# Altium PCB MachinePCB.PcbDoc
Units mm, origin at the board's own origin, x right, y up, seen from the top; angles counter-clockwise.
Board outline 152.4 x 101.6 mm, 2 copper layers (Top Layer, Bottom Layer); 66 components, 31 nets, 228 pads, 37 vias.
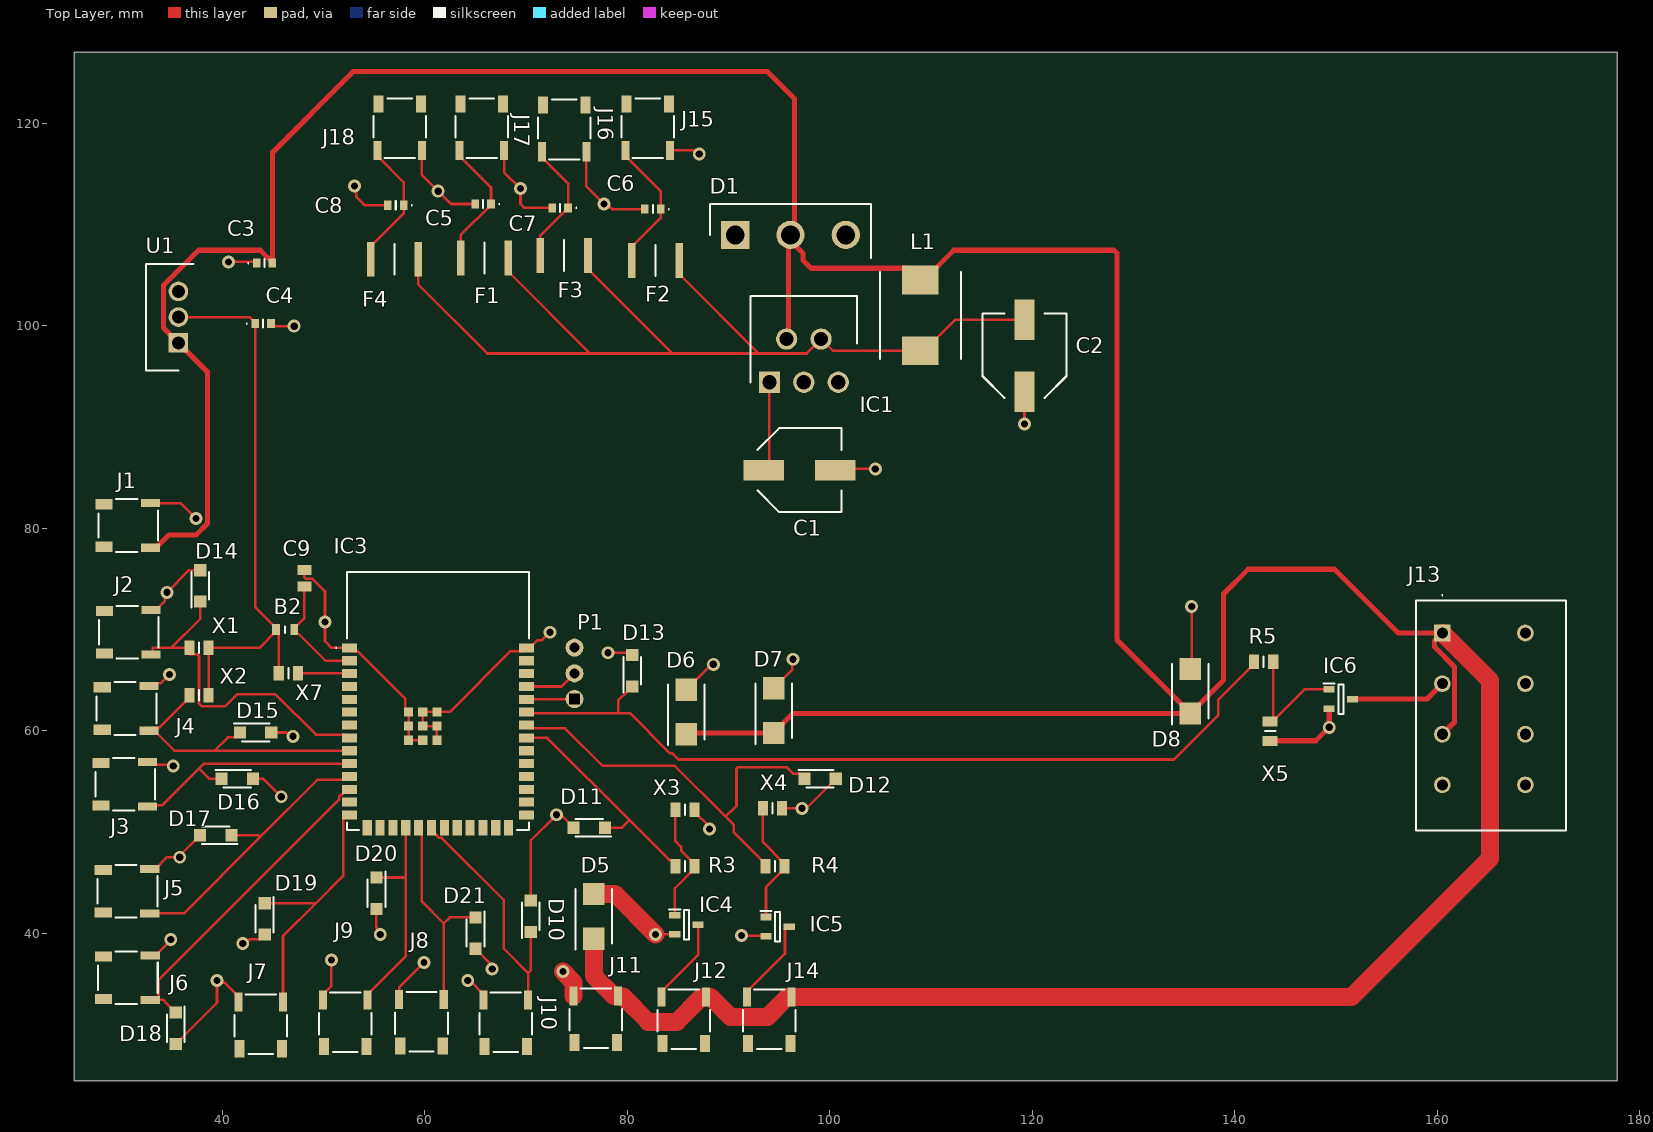
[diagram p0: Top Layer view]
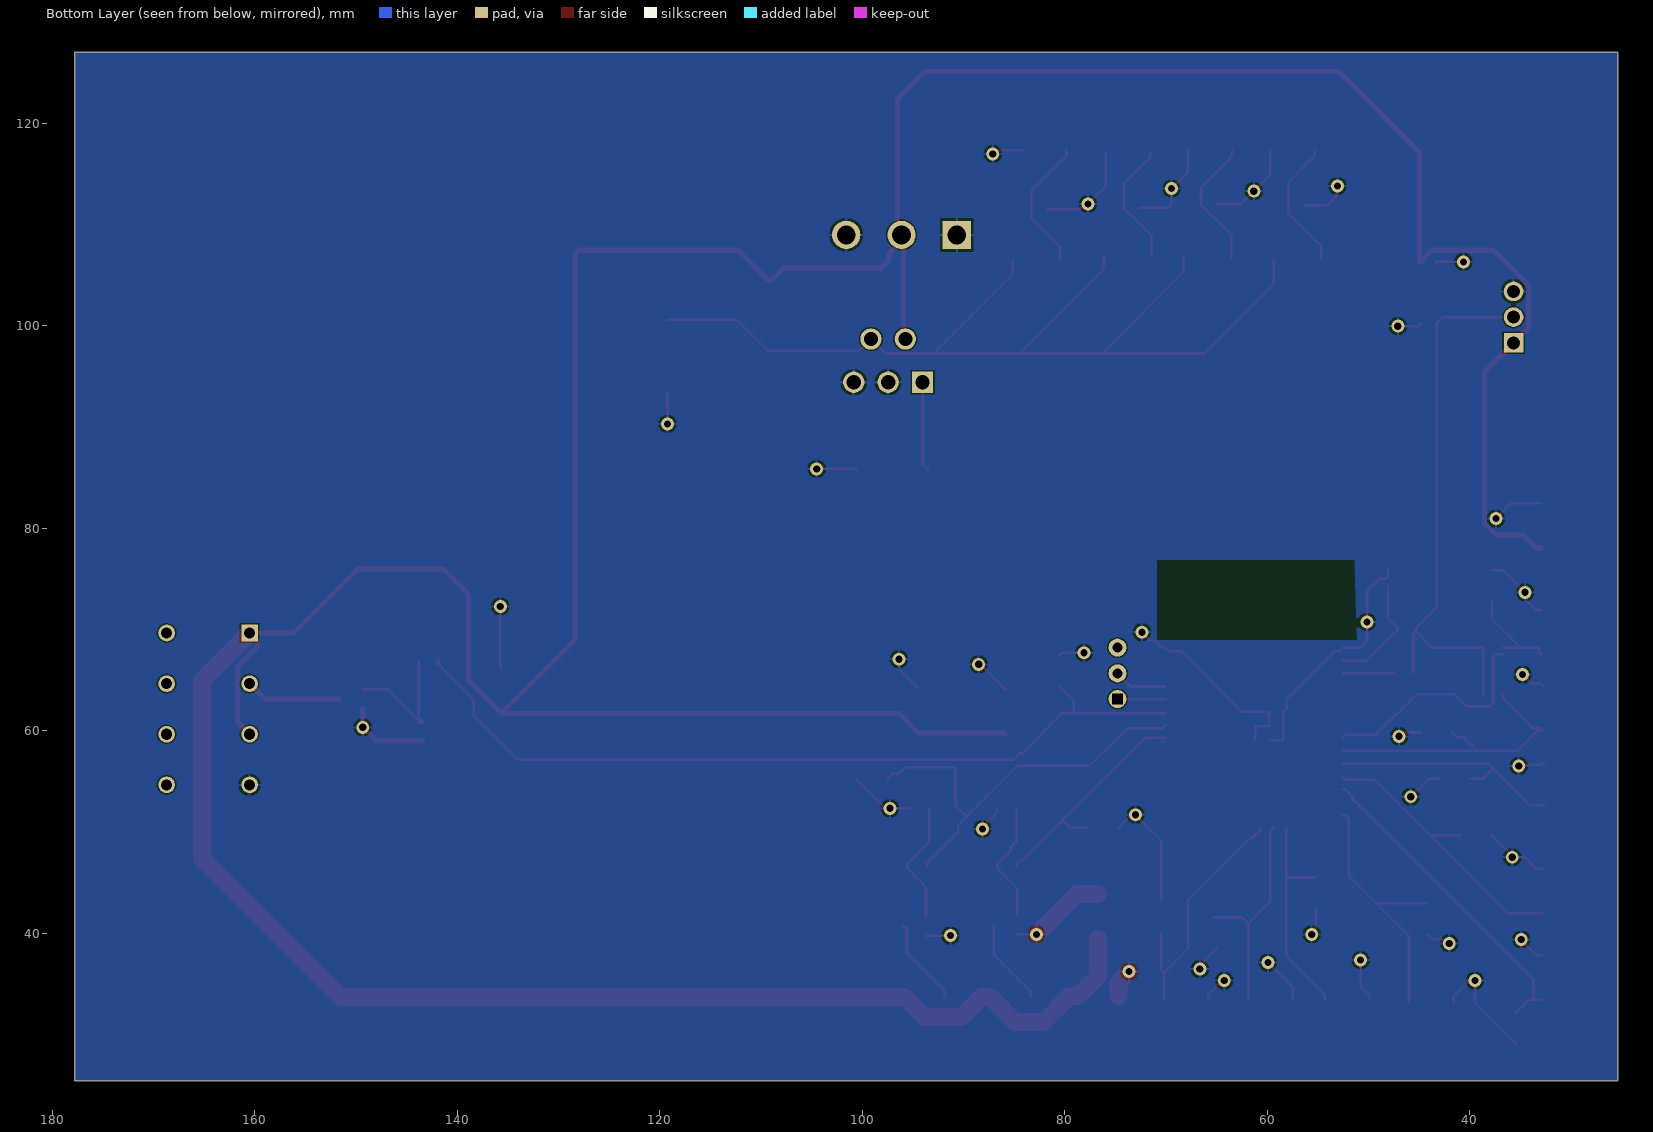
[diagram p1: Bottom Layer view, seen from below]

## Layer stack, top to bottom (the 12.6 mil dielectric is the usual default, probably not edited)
Top Solder: solder mask 0.0102, Solder Resist, Dk 3.5
Top Layer: signal copper 0.0356
Dielectric 1: dielectric 0.32, FR-4, Dk 4.8
Bottom Layer: signal copper 0.0356
Bottom Solder: solder mask 0.0102, Solder Resist, Dk 3.5

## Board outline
25.4,25.4 177.8,25.4 177.8,127 25.4,127

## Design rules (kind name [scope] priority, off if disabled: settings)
Clearance [All] p1: gap=0.127 ignorepadtopadclearanceinfootprint=FALSE
PolygonConnect [All] p1: connectstyle=Relief reliefconductorwidth=0.254 reliefentries=4 polygonreliefangle="90 Angle" airgapwidth=0.254
RoutingVias [All] p1: holewidth=0.711 width=1.27 viastyle="Through Hole" minholewidth=0.711 minwidth=1.27 maxholewidth=0.711 maxwidth=1.27
SilkToSolderMaskClearance [IsPad] p1: minsilkscreentomaskgap=0.051 clearancetoexposedcopper=TRUE
SolderMaskExpansion [All] p1: expansion=0.05 istentingtop=FALSE
SupplyNets "Schematic Supply Nets" [InNet('GND')] p1: voltage=0.000
Width [All] p1: maxlimit=2.54 minlimit=0.254 preferedwidth=0.254 bottomlayer_maxwidth=0.254 minimp=50.000000 maximp=50.000000 favimp=50.000000
29 further rules are at their usual default settings.

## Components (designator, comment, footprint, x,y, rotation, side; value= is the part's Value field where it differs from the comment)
B2 "MF-FSML100_8-2" FUSC1608X70N 46.228,69.977 r0 top
C1 "220 uF" EEHZT1E331UP 97.028,85.725 r0 top
C2 "220 uF" EEHZT1E331UP 119.253,97.028 r90 top
C3 "10 uF" ZRB18x 44.196,106.172 r0 top
C4 "10 uF" ZRB18x 44.056,100.203 r0 top
C5 "ZRB18AR61E106KE01L" ZRB18x 65.786,112.014 r180 top
C6 "ZRB18AR61E106KE01L" ZRB18x 82.537,111.506 r180 top
C7 "ZRB18AR61E106KE01L" ZRB18x 73.393,111.633 r180 top
C8 "ZRB18AR61E106KE01L" ZRB18x 57.15,111.887 r180 top
C9 "0.1 uF" CAPC2012X125N 48.133,75.057 r270 top
D1 "VS-40CPQ045-N3" TO546P531X1558X2499-3P 90.679,108.966 r0 top
D5 "TPSMB12A-VR" DIOM5436X244N 76.708,41.656 r90 top
D6 "TPSMB12A-VR" DIOM5436X244N 85.852,61.849 r90 top
D7 "TPSMB12A-VR" DIOM5436X244N 94.488,61.976 r90 top
D8 "TPSMB12A-VR" DIOM5436X244N 135.636,63.881 r90 top
D10 "SMF5.0A" SODFL3618X110N 70.485,41.656 r90 top
D11 "SMF5.0A" SODFL3618X110N 76.271,50.412 r180 top
D12 "SMF5.0A" SODFL3618X110N 99.06,55.245 r0 top
D13 "SMF5.0A" SODFL3618X110N 80.518,65.913 r90 top
D14 "SMF5.0A" SODFL3618X110N 37.846,74.295 r90 top
D15 "SMF5.0A" SODFL3618X110N 43.307,59.817 r0 top
D16 "SMF5.0A" SODFL3618X110N 41.503,55.245 r0 top
D17 "SMF5.0A" SODFL3618X110N 39.37,49.657 r180 top
D18 "SMF5.0A" SODFL3618X110N 35.433,30.607 r270 top
D19 "SMF5.0A" SODFL3618X110N 44.196,41.402 r270 top
D20 "SMF5.0A" SODFL3618X110N 55.245,43.942 r270 top
D21 "SMF5.0A" SODFL3618X110N 65.024,40.005 r270 top
F1 "PTS18126V300" FUSC4632X120N#1 65.913,106.68 r180 top
F2 "PTS18126V300" FUSC4632X120N#1 82.804,106.426 r180 top
F3 "PTS18126V300" FUSC4632X120N#2 73.787,106.934 r180 top
F4 "PTS18126V300" FUSC4632X120N#1 57.023,106.553 r180 top
IC1 "LM2596T-5.0_LF03" TO170P470X1028X2142-5P 94.058,94.409 r0 top
IC3 "ESP32-S3-WROOM-1-N4" ESP32S3WROOM1N4 61.317,62.662 r0 top
IC4 "NDS355AN" SOT95P251X112-3N 85.859,40.828 r0 top
IC5 "NDS355AN" SOT95P251X112-3N 94.869,40.64 r0 top
IC6 "NDS355AN" SOT95P251X112-3N 150.495,63.119 r0 top
J1 "SM02B-SFHLS-TF_LF__SN_" SM02BSFHLSTFLFSN 30.734,80.264 r180 top
J2 "SM02B-SFHLS-TF_LF__SN_" SM02BSFHLSTFLFSN 30.779,69.723 r180 top
J3 "SM02B-SFHLS-TF_LF__SN_" SM02BSFHLSTFLFSN 30.439,54.696 r180 top
J4 "SM02B-SFHLS-TF_LF__SN_" SM02BSFHLSTFLFSN 30.566,62.189 r180 top
J5 "SM02B-SFHLS-TF_LF__SN_" SM02BSFHLSTFLFSN 30.661,44.148 r180 top
J6 "SM02B-SFHLS-TF_LF__SN_" SM02BSFHLSTFLFSN 30.693,35.601 r180 top
J7 "SM02B-SFHLS-TF_LF__SN_" SM02BSFHLSTFLFSN 43.815,30.988 r270 top
J8 "SM02B-SFHLS-TF_LF__SN_" SM02BSFHLSTFLFSN 59.69,31.242 r270 top
J9 "SM02B-SFHLS-TF_LF__SN_" SM02BSFHLSTFLFSN 52.156,31.201 r270 top
J10 "SM02B-SFHLS-TF_LF__SN_" SM02BSFHLSTFLFSN 68.031,31.201 r270 top
J11 "SM02B-SFHLS-TF_LF__SN_" SM02BSFHLSTFLFSN 76.921,31.582 r270 top
J12 "SM02B-SFHLS-TF_LF__SN_" SM02BSFHLSTFLFSN 85.598,31.496 r270 top
J13 "1330200000" 1330200000 160.528,69.643 r270 top
J14 "SM02B-SFHLS-TF_LF__SN_" SM02BSFHLSTFLFSN 94.048,31.483 r270 top
J15 "SM02B-SFHLS-TF_LF__SN_" SM02BSFHLSTFLFSN 82.042,119.507 r90 top
J16 "SM02B-SFHLS-TF_LF__SN_" SM02BSFHLSTFLFSN 73.787,119.38 r90 top
J17 "SM02B-SFHLS-TF_LF__SN_" SM02BSFHLSTFLFSN 65.659,119.507 r90 top
J18 "SM02B-SFHLS-TF_LF__SN_" SM02BSFHLSTFLFSN 57.531,119.507 r90 top
L1 "33 uH" INDPM8680X400N 108.966,101.021 r270 top
P1 "PREC003SAAN-RC" PCBComponent_1 74.803,65.659 r90 top
R3 "100" RESC2012X55N 85.725,46.609 r0 top
R4 "100" RESC2012X55N 94.615,46.609 r0 top
R5 "100" RESC2012X55N 142.875,66.802 r0 top
U1 "LMS1585ACT-3.3_NOPB" TO254P470X1028X1955-3P 35.687,98.298 r90 top
X1 "4.7k" RESC2012X65N 37.719,68.172 r0 top
X2 "4.7k" RESC2012X65N 37.719,63.5 r0 top
X3 "4.7k" RESC2012X65N 85.725,52.197 r0 top
X4 "4.7k" RESC2012X65N 94.361,52.324 r0 top
X5 "4.7k" RESC2012X65N 143.51,59.944 r270 top
X7 "4.7k" RESC2012X65N 46.543,65.659 r180 top

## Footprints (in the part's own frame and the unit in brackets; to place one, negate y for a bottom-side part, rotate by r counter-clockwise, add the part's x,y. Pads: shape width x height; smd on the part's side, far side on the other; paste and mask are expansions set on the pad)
1330200000 [mm]
  rect 1.65x1.65 hole 1.1: A1(0,0)
  round 1.65 hole 1.1: A2(5,0) A3(10,0) A4(15,0) B1(0,8.2) B2(5,8.2) B3(10,8.2) B4(15,8.2)
  silkscreen extent -3.8,-2.6 19.5,12.2
CAPC2012X125N [mm]
  rect 0.99x1.39 smd: 1(-0.82,0) 2(0.82,0)
DIOM5436X244N [mm]
  rect 2.2x2.15 smd: 1(-2.2,0) 2(2.2,0)
  silkscreen extent -3.27,-1.81 2.7,1.81, body extent -2.7,-1.81 2.7,1.81, height 2.44
EEHZT1E331UP [mm]
  rect 4x2 smd: 1(-3.55,0) 2(3.55,0)
  silkscreen extent -4.15,-4.15 4.15,4.15, body extent -4.79,-4.15 4.91,4.15, height 10.2
ESP32S3WROOM1N4 [mm]
  rect 1.5x0.9 smd: 1(-8.75,5.51) 2(-8.75,4.24) 3(-8.75,2.97) 4(-8.75,1.7) 5(-8.75,0.43) 6(-8.75,-0.84) 7(-8.75,-2.11) 8(-8.75,-3.38) 9(-8.75,-4.65) 10(-8.75,-5.92) 11(-8.75,-7.19) 12(-8.75,-8.46) 13(-8.75,-9.73) 14(-8.75,-11) 27(8.75,-11) 28(8.75,-9.73) 29(8.75,-8.46) 30(8.75,-7.19) 31(8.75,-5.92) 32(8.75,-4.65) 33(8.75,-3.38) 34(8.75,-2.11) 35(8.75,-0.84) 36(8.75,0.43) 37(8.75,1.7) 38(8.75,2.97) 39(8.75,4.24) 40(8.75,5.51)
  rect 0.9x1.5 smd: 15(-6.985,-12.25) 16(-5.715,-12.25) 17(-4.445,-12.25) 18(-3.175,-12.25) 19(-1.905,-12.25) 20(-0.635,-12.25) 21(0.635,-12.25) 22(1.905,-12.25) 23(3.175,-12.25) 24(4.445,-12.25) 25(5.715,-12.25) 26(6.985,-12.25)
  rect 0.9x0.9 smd: 41(-1.5,-2.21) 42(-0.1,-2.21) 43(-0.1,-0.81) 44(-1.5,-0.81) 45(-2.9,-0.81) 46(-2.9,-2.21) 47(-2.9,-3.61) 48(-1.5,-3.61) 49(-0.1,-3.61)
  silkscreen extent -10.1,-12.5 9,13
FUSC1608X70N [mm]
  rect 0.77x1.07 smd: 1(-0.9,0) 2(0.9,0)
  silkscreen extent 0,-0.33 0,0.33
FUSC4632X120N#1 [mm]
  rect 0.75x3.43 smd: 1(-2.35,0) 2(2.35,0)
  silkscreen extent 0,-1.52 0,1.52
FUSC4632X120N#2 [mm]
  rect 0.75x3.43 smd: 1(-2.35,0) " "(2.35,0)
  silkscreen extent 0,-1.52 0,1.52
INDPM8680X400N [mm]
  rect 2.85x3.6 smd: 1(-3.5,0) 2(3.5,0)
  silkscreen extent -4.3,-4 4.3,4
PCBComponent_1 [mm]
  round 1.78 hole 1 square: 1(-2.54,0)
  round 1.78 hole 1: 2(0,0) 3(2.54,0)
RESC2012X55N [mm]
  rect 1x1.45 smd: 1(-0.95,0) 2(0.95,0)
  silkscreen extent 0,-0.53 0,0.53
RESC2012X65N [mm]
  rect 1x1.45 smd: 1(-0.95,0) 2(0.95,0)
  silkscreen extent 0,-0.53 0,0.53
SM02BSFHLSTFLFSN [mm]
  rect 1.7x1 smd: 1(2.4,2.1) 2(2.4,-2.1)
  rect 1.9x0.8 smd: MP1(-2.2,2.2) MP2(-2.2,-2.2)
  silkscreen extent -2.95,-2.6 2.95,2.6
SODFL3618X110N [mm]
  rect 1.2x1.22 smd: 1(-1.55,0) 2(1.55,0)
  silkscreen extent -2.15,-0.87 1.35,0.87
SOT95P251X112-3N [mm]
  rect 1.1x0.65 smd: 1(-1.15,0.95) 2(-1.15,-0.95) 3(1.15,0)
  silkscreen extent -1.7,-1.46 0.25,1.53
TO170P470X1028X2142-5P [mm]
  rect 2.1x2.1 / inner round 2.1 / far side rect 2.1x2.1 hole 1.4: 1(0,0)
  round 2.1 hole 1.4: 2(1.7,4.27) 3(3.4,0) 4(5.1,4.27) 5(6.8,0)
  silkscreen extent -1.87,0 8.67,8.53
TO254P470X1028X1955-3P [mm]
  rect 1.935x1.935 / inner round 1.935 / far side rect 1.935x1.935 hole 1.29: 1(0,0)
  round 1.935 hole 1.29: 2(2.54,0) 3(5.08,0)
  silkscreen extent -2.73,-1.5 7.81,3.2
TO546P531X1558X2499-3P [mm]
  rect 2.79x2.79 / inner round 2.79 / far side rect 2.79x2.79 hole 1.86: 1(0,0)
  round 2.79 hole 1.86: 2(5.46,0) 3(10.92,0)
  silkscreen extent -2.47,-2.27 13.39,3.04
ZRB18x [mm]
  rect 0.75x0.9 smd: 1(-0.775,0) 2(0.775,0)
  silkscreen extent -1.65,-0.4 0,0.4

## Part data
B2: "Resettable Fuses - PPTC 8V     1A", Manufacturer_Name=Bourns, Manufacturer_Part_Number=MF-FSML100/8-2, Mouser Part Number=652-MF-FSML100/8-2
C1 C2: library part EEE-TP1C221AP, "Capacitor Polarised", Manufacturer_Name=Panasonic, Mouser Part Number=667-EEE-TP1C221AP
C3 C4: library part ZRB18AR61E106KE01L, Manufacturer_Name="Murata Electronics"
C5 C6 C7 C8: "Capacitor", Manufacturer_Name="Murata Electronics"
C9: library part 885382207007, "WCAP-CSST Soft Termination MLCC X7R0805104K050DFCT1S000; SMT Chip; 100 nF +/- 10%; 50 V(DC); -55C / +125C; size 0805; LxWxH 2.0 x 1.25 x 1.25; Term. Ag-Polymer/Ni/Sn", Manufacturer_Name="Wurth Elektronik", Mouser Part Number=710-885382207007
D1: "Diode", Manufacturer_Name=Vishay, Mouser Part Number=78-VS-40CPQ045-N3
D5 D6 D7 D8: "TVS Diode (Uni-directional)", Manufacturer_Name=LITTELFUSE, Mouser Part Number=576-TPSMB12A-VR
D10 D11 D12 D13 D14 D15 D16 D17 D18 D19 D20 D21: "LITTELFUSE - SMF5.0A - TVS DIODE, 200W, 5V, UNIDIR, SOD-123FL", Manufacturer_Name=LITTELFUSE, Mouser Part Number=576-SMF5.0A
F1 F2 F3 F4: "PPTC SMD 1812 6V 3.0A", Manufacturer_Name=Eaton, Mouser Part Number=504-PTS18126V300
IC1: "Integrated Circuit", Arrow Part Number=LM2596T-5.0/LF03, Manufacturer_Name="Texas Instruments", Mouser Part Number=926-LM2596T-50/LF03
IC3: "Integrated Circuit", Manufacturer_Name="Espressif Systems", Mouser Part Number=356-ESP32-S3WROOM1N4
IC4 IC5 IC6: "Integrated Circuit", Manufacturer_Name=onsemi, Mouser Part Number=512-NDS355AN
J1 J2 J3 J4 J5 J6 J7 J8 J9 J10 J11 J12 J14 J15 J16 J17 J18: "CONN HEADER SMD R/A 2POS 1.8MM", Manufacturer_Name="JST (JAPAN SOLDERLESS TERMINALS)", Manufacturer_Part_Number=SM02B-SFHLS-TF(LF)(SN), Mouser Part Number=306-SM02BSFHLSTFLFSN
J13: "Connector", Manufacturer_Name=Weidmuller, Mouser Part Number=470-1330200000
L1: library part F1F2-0804-330M, "Inductor", Manufacturer_Name=Bel
P1: "ESP32 USB Connector"
R3 R4 R5: library part TNPW0805100RBEEA, "Resistor", Manufacturer_Name=Vishay, Mouser Part Number=71-TNPW0805100RBEEA
U1: "Undefined or Miscellaneous", Arrow Part Number=LMS1585ACT-3.3/NOPB, Manufacturer_Name="Texas Instruments", Mouser Part Number=926-LMS1585ACT33NOPB
X1 X2 X3 X4 X5 X7: library part CPF0805B4K7E1, Manufacturer_Name="TE Connectivity", Mouser Part Number=279-CPF0805B4K7E1

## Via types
v1: diameter 1.27, hole 0.711, Top Layer to Bottom Layer, 37 vias

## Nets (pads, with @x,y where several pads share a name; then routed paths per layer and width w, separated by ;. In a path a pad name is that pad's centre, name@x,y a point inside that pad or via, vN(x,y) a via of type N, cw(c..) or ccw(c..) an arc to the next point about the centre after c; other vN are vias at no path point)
12_IN: C3.2 D1.2 D5.1 D6.1 D7.1 D8.1 IC1.2 J1.MP1 J11.MP1 J12.MP1 J13.A1 J13.A3 J14.MP1 L1.1 U1.1 | length 445.3
  Top Layer w0.508: J1.MP1 33.484,78.064 34.758,79.338 37.441,79.338 38.568,80.465 38.568,95.417 U1.1 34.211,99.774 34.211,103.989 37.664,107.442 43.776,107.442 44.971,106.247 C3.2 44.971,117.107 52.959,125.095 93.853,125.095 96.52,122.428 96.52,109.347 D1.2 ; D6.1 85.979,59.776 D7.1 ; D7.1@94.488,59.801 96.368,61.681 D8.1 D8.1@135.636,61.706 ; IC1.2 95.948,98.87 D1.2@95.948,108.384 ; D1.2@96.139,108.384 97.373,107.15 97.373,106.462 98.171,105.664 107.823,105.664 L1.1 109.341,104.521 112.262,107.442 128.099,107.442 128.397,107.144 128.397,68.945 D8.1@135.636,61.706 ; J13.A3 161.734,60.849 161.734,66.29 159.766,68.258 159.766,68.881 J13.A1 156.163,69.643 149.86,75.946 141.351,75.946 138.904,73.499 138.904,64.974 D8.1@135.636,61.706
  Top Layer w1.778: D5.1@76.708,39.431 76.708,35.767 78.693,33.782 J11.MP1 ; 79.61,33.721 82.089,31.242 84.916,31.242 87.309,33.635 ; J12.MP1 88.226,33.696 90.205,31.717 93.854,31.717 95.82,33.683 J14.MP1 151.539,33.683 165.227,47.371 165.227,64.944 J13.A1
+3.3V: B2.1 C4.1 U1.2 X1.2 X2.2 X7.2 | length 55.3
  Top Layer w0.254: U1.2 42.721,100.838 43.281,100.278 C4.1 43.281,72.174 45.328,70.127 B2.1 ; X2.2 X1.2 43.673,68.172 45.328,69.827 45.593,69.562 X7.2
+5V: C2.2 F1.1 F2.1 F3.1 F4.1 IC1.4 L1.2 | length 105.9
  Top Layer w0.254: F4.1 59.373,104.076 66.201,97.248 76.355,97.248 ; F1.1 68.263,105.34 76.355,97.248 ; F3.1 76.137,105.594 84.483,97.248 ; F2.1 85.154,105.086 92.992,97.248 ; C2.2 112.398,100.578 109.341,97.521 L1.2 100.316,97.521 IC1.4 97.727,97.248 92.992,97.248 ; 76.355,97.248 84.483,97.248 ; 84.483,97.248 92.992,97.248
FLOW: D15.1 IC3.9 J4.MP1 X2.1 | length 29.1
  Top Layer w0.254: J4.MP1 33.316,59.989 35.293,58.012 39.243,58.012 ; J4.MP1@33.039,60.262 33.756,60.262 36.769,63.275 X2.1 ; D15.1 41.757,59.807 41.284,59.334 40.565,59.334 39.243,58.012 ; IC3.9 39.243,58.012
GND: C1.2 C2.1 C3.1 C4.2 C5.2 C6.2 C7.2 C8.2 C9.1 D1.1 D1.3 D5.2 D6.2 D7.2 D8.2 D10.2 D11.2 D12.2 D13.2 D14.2 D15.2 D16.2 D17.2 D18.2 D19.2 D20.2 D21.2 IC1.3 IC1.5 IC3.1 IC3.40 IC3.41 IC3.42 IC3.43 IC3.44 IC3.45 IC3.46 IC3.47 IC3.48 IC3.49 IC4.2 IC5.2 IC6.2 J1.MP2 J2.MP2 J3.MP2 J4.MP2 J5.MP2 J6.MP2 J7.MP2 J8.MP2 J9.MP2 J10.MP2 J11.MP2 J13.A4 J15.MP2 J16.MP2 J17.MP2 J18.MP2 U1.3 X3.2 X4.2 X5.2 | length 215.6
  Top Layer w0.254: J3.MP2 32.912,56.623 35.071,56.623 v1(35.179,56.515) ; J4.MP2 33.039,64.662 33.928,64.662 v1(34.798,65.532) ; J5.MP2 33.411,46.348 34.561,47.498 v1(35.814,47.498) 35.814,47.641 37.82,49.647 D17.2 ; J6.MP2 33.443,37.801 34.925,39.283 v1(34.925,39.37) ; J2.MP2@32.934,71.923 33.484,71.923 34.35,72.789 34.35,73.466 v1(34.544,73.66) 36.729,75.845 D14.2 ; J1.MP2 35.9,82.464 v1(37.425,80.939) ; D18.2 35.443,29.057 35.916,29.53 35.916,29.54 39.497,33.121 v1(39.497,35.306) 39.691,35.112 40.241,35.112 41.615,33.738 J7.MP2 ; v1(40.64,106.299) 43.294,106.299 C3.1 ; v1(42.037,38.989) 42.312,38.989 42.702,39.379 43.723,39.379 D19.2 ; D16.2 44.069,55.245 v1(45.847,53.467) ; C4.2 44.831,100.197 45.079,99.949 v1(47.117,99.949) ; D15.2 46.334,59.817 46.715,59.436 v1(46.99,59.436) ; C9.1 48.133,75.135 48.282,74.986 48.933,74.986 50.165,73.754 v1(50.165,70.739) 50.165,68.834 50.827,68.172 IC3.1 52.89,67.849 53.359,67.849 58.094,63.114 58.094,62.175 IC3.45 IC3.46 IC3.47 IC3.48 ; J9.MP2 49.956,33.951 50.8,34.795 v1(50.8,37.338) ; v1(53.086,113.792) 53.234,113.644 53.234,112.776 54.123,111.887 C8.2 ; D20.2 55.245,40.534 55.626,40.153 v1(55.626,39.878) ; J8.MP2 57.49,34.63 v1(59.944,37.084) ; J18.MP2 59.731,114.894 v1(61.341,113.284) 62.611,112.014 C5.2 ; IC3.49 IC3.42 IC3.41 IC3.44 IC3.43 62.494,61.852 68.491,67.849 69.744,67.849 IC3.40 70.367,68.172 71.138,68.943 71.61,68.943 v1(72.39,69.723) ; v1(64.262,35.306) 64.476,35.306 65.831,33.951 J10.MP2 ; D21.2 65.034,38.455 66.481,37.008 66.481,36.643 v1(66.675,36.449) ; J17.MP2 67.859,115.148 v1(69.469,113.538) 69.469,112.035 69.871,111.633 C7.2 ; D10.2 70.485,49.149 v1(73.025,51.689) 73.219,51.495 73.648,51.495 74.721,50.422 D11.2 ; J16.MP2 75.987,113.751 v1(77.724,112.014) 77.999,112.014 78.507,111.506 C6.2 ; v1(78.105,67.691) 80.29,67.691 D13.2 ; v1(82.804,39.878) IC4.2 ; J15.MP2 86.507,117.307 86.847,116.967 v1(87.122,116.967) ; D6.2 85.852,64.074 88.326,66.548 v1(88.519,66.548) ; X3.2 86.675,51.972 88.138,50.509 v1(88.138,50.292) ; v1(91.313,39.751) 91.344,39.72 93.688,39.72 IC5.2 ; D7.2 94.488,64.201 96.327,66.04 96.327,66.99 v1(96.393,67.056) ; X4.2 v1(97.282,52.324) 97.476,52.518 97.893,52.518 100.61,55.235 D12.2 ; C1.2 100.705,85.852 v1(104.521,85.852) ; v1(119.253,90.297) C2.1 ; D8.2 135.763,66.208 v1(135.763,72.263) ; IC6.2 IC6.2@149.352,62.162
  Top Layer w0.508: X5.2 148.021,58.994 v1(149.352,60.325) IC6.2@149.352,62.162
  Top Layer w1.778: v1(73.66,36.195) 74.721,35.134 J11.MP2 ; D5.2 78.826,43.856 v1(82.804,39.878)
HX711_ADC: D16.1 IC3.10 J3.MP1 | length 24.3
  Top Layer w0.254: J3.MP1 32.76,52.617 34.075,52.617 37.719,56.261 ; D16.1 38.735,55.245 37.719,56.261 ; IC3.10 38.2,56.742 37.719,56.261
HX711_ADC2: D20.1 IC3.18 J9.MP1 | length 21.5
  Top Layer w0.254: J9.MP1 54.356,33.951 58.142,37.737 58.142,45.466 ; D20.1 58.116,45.492 58.142,45.466 ; IC3.18 58.142,45.466
HX711_CLK1: D19.1 IC3.14 J7.MP1 | length 26.4
  Top Layer w0.254: D19.1 49.25,42.952 49.253,42.949 ; J7.MP1 46.015,39.71 49.253,42.949 ; IC3.14 52.267,51.662 51.944,51.339 51.944,45.639 49.253,42.949
HX711_CLK2: D21.1 IC3.19 J8.MP1 | length 21.6
  Top Layer w0.254: IC3.19 59.735,50.089 59.735,43.104 61.89,40.949 ; J8.MP1 61.89,40.949 ; D21.1@65.287,41.555 62.496,41.555 61.89,40.949
MOTOR_DIR: D10.1 IC3.20 J10.MP1 | length 25.3
  Top Layer w0.254: IC3.20 60.682,50.112 61.005,49.789 61.099,49.789 61.248,49.64 61.248,49.557 61.397,49.408 61.686,49.408 67.818,43.276 67.818,38.481 70.231,36.068 ; J10.MP1 70.231,36.068 ; D10.1 70.485,36.322 70.231,36.068
MOTOR_PWM: D17.1 IC3.11 J5.MP1 | length 28.2
  Top Layer w0.254: J5.MP1 36.214,41.948 43.742,49.476 ; D17.1 43.561,49.657 43.742,49.476 ; IC3.11 52.244,55.149 49.415,55.149 43.742,49.476
NetB2_2: B2.2 C9.2 IC3.2 | length 11.5
  Top Layer w0.254: C9.2 48.133,71.132 47.128,70.127 47.128,69.827 47.386,69.569 47.536,69.569 50.203,66.902 IC3.2
NetC1_1: C1.1 IC1.1 | length 8.9
  Top Layer w0.254: C1.1 94.058,86.305 IC1.1
NetC5_1: C5.1 F1.2 J17.MP1 | length 13.2
  Top Layer w0.254: J17.MP1 63.459,116.757 66.561,113.655 C5.1 66.561,111.939 63.563,108.941 F1.2
NetC6_1: C6.1 F2.2 J15.MP1 | length 13.5
  Top Layer w0.254: J15.MP1 79.842,116.757 83.312,113.287 C6.1 83.312,110.624 80.454,107.766 F2.2
NetC7_1: "F3. " C7.1 J16.MP1 | length 12.5
  Top Layer w0.254: 71.437,106.934 71.437,108.902 73.845,111.31 73.92,111.31 74.168,111.558 C7.1 74.168,114.049 71.587,116.63 J16.MP1
NetC8_1: C8.1 F4.2 J18.MP1 | length 13.2
  Top Layer w0.254: F4.2 54.673,107.893 54.921,108.141 55.01,108.141 57.925,111.056 C8.1 57.925,114.163 55.331,116.757 J18.MP1
NetIC3_3: IC3.3 X7.1 | length 5.1
  Top Layer w0.254: X7.1 52.54,65.659 IC3.3
NetIC3_36: IC3.36 P1.1 | length 4.7
  Top Layer w0.254: IC3.36 70.094,63.119 P1.1
NetIC3_37: IC3.37 P1.2 | length 5.3
  Top Layer w0.254: IC3.37 73.506,64.362 P1.2
NetIC4_1: IC4.1 R3.2 X3.1 | length 12
  Top Layer w0.254: IC4.1 84.709,44.418 86.675,46.384 R3.2 86.675,46.834 85.344,48.165 85.344,48.514 84.775,49.083 X3.1
NetIC4_3: IC4.3 J12.MP2 | length 8.6
  Top Layer w0.254: J12.MP2 83.398,34.246 87.009,37.857 IC4.3
NetIC5_1: IC5.1 R4.2 X4.1 | length 12.4
  Top Layer w0.254: X4.1 93.411,48.988 95.565,46.834 R4.2 95.565,46.384 93.719,44.538 IC5.1
NetIC5_3: IC5.3 J14.MP2 | length 8.8
  Top Layer w0.254: J14.MP2 91.848,34.233 95.596,37.981 95.596,40.442 95.794,40.64 IC5.3
NetIC6_1: IC6.1 R5.2 X5.1 | length 13.2
  Top Layer w0.254: X5.1@143.735,60.894 146.91,64.069 IC6.1 ; X5.1@143.825,61.14 R5.2
  Top Layer w0.508: X5.1 X5.1@143.735,60.894 ; X5.1@143.579,60.894 X5.1@143.825,61.14
NetIC6_3: IC6.3 J13.A2 | length 9.5
  Top Layer w0.508: IC6.3 159.004,63.119 J13.A2
PUMP_1: D11.1 IC3.33 R3.1 | length 23.3
  Top Layer w0.254: IC3.33@70.39,58.959 IC3.33 72.102,59.282 80.233,51.15 ; D11.1 79.495,50.412 80.233,51.15 ; R3.1 84.775,46.834 84.402,47.207 84.177,47.207 80.233,51.15
PUMP_2: D12.1 IC3.34 R4.1 | length 42.4
  Top Layer w0.254: IC3.34 70.39,60.229 73.883,60.229 77.597,56.515 84.709,56.515 89.725,51.498 ; R4.1 93.665,46.834 90.551,49.948 90.551,50.673 89.725,51.498 ; D12.1 97.51,55.255 97.037,55.728 96.418,55.728 95.758,56.388 90.954,56.388 90.805,56.239 90.805,52.578 89.725,51.498
SOL: D13.1 IC3.35 R5.1 | length 82.3
  Top Layer w0.254: IC3.35 IC3.35@70.168,61.721 ; IC3.35@70.39,61.499 IC3.35@70.168,61.721 ; D13.1 80.508,64.363 80.035,63.89 80.035,63.88 79.121,62.966 79.121,61.721 ; R5.1@141.925,66.577 138.41,63.062 138.41,61.562 133.998,57.15 85.09,57.15 84.455,57.785 84.201,57.785 80.265,61.721 79.121,61.721 ; IC3.35@70.168,61.721 79.121,61.721
  Top Layer w0.508: R5.1@141.925,66.577 R5.1
SSR: D18.1 IC3.12 J6.MP1 | length 32.6
  Top Layer w0.254: D18.1 35.423,32.157 34.569,33.011 34.569,33.021 34.189,33.401 J6.MP1 33.443,33.401 33.716,33.674 33.716,35.351 51.563,53.198 51.563,53.487 51.712,53.636 51.795,53.636 51.944,53.785 51.944,53.879 52.267,54.202 IC3.12
WATER_TEMP: D14.1 IC3.8 J2.MP1 X1.1 | length 33
  Top Layer w0.254: J2.MP1 33.169,67.713 33.169,68.172 34.969,68.172 ; X1.1@36.769,67.523 37.554,67.523 37.719,67.358 37.719,62.686 38.011,62.394 40.295,62.394 41.489,63.588 45.269,63.588 49.252,59.605 52.244,59.605 IC3.8 ; X1.1 34.969,68.172 ; D14.1 37.846,71.049 34.969,68.172
pads on no net: IC3.4 IC3.5 IC3.6 IC3.7 IC3.13 IC3.15 IC3.16 IC3.17 IC3.21 IC3.22 IC3.23 IC3.24 IC3.25 IC3.26 IC3.27 IC3.28 IC3.29 IC3.30 IC3.31 IC3.32 IC3.38 IC3.39 J1.1 J1.2 J2.1 J2.2 J3.1 J3.2 J4.1 J4.2 J5.1 J5.2 J6.1 J6.2 J7.1 J7.2 J8.1 J8.2 J9.1 J9.2 J10.1 J10.2 J11.1 J11.2 J12.1 J12.2 J13.B1 J13.B2 J13.B3 J13.B4 J14.1 J14.2 J15.1 J15.2 J16.1 J16.2 J17.1 J17.2 J18.1 J18.2 P1.3

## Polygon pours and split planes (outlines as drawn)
GND on Bottom Layer "3" (solid, pour order 0): 25.445,127 177.845,127 177.845,25.4 25.445,25.4

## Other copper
Bottom Layer:
  pour cut-out: 51.435,76.835 70.993,76.835 70.866,76.708 70.866,68.961 51.181,68.961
